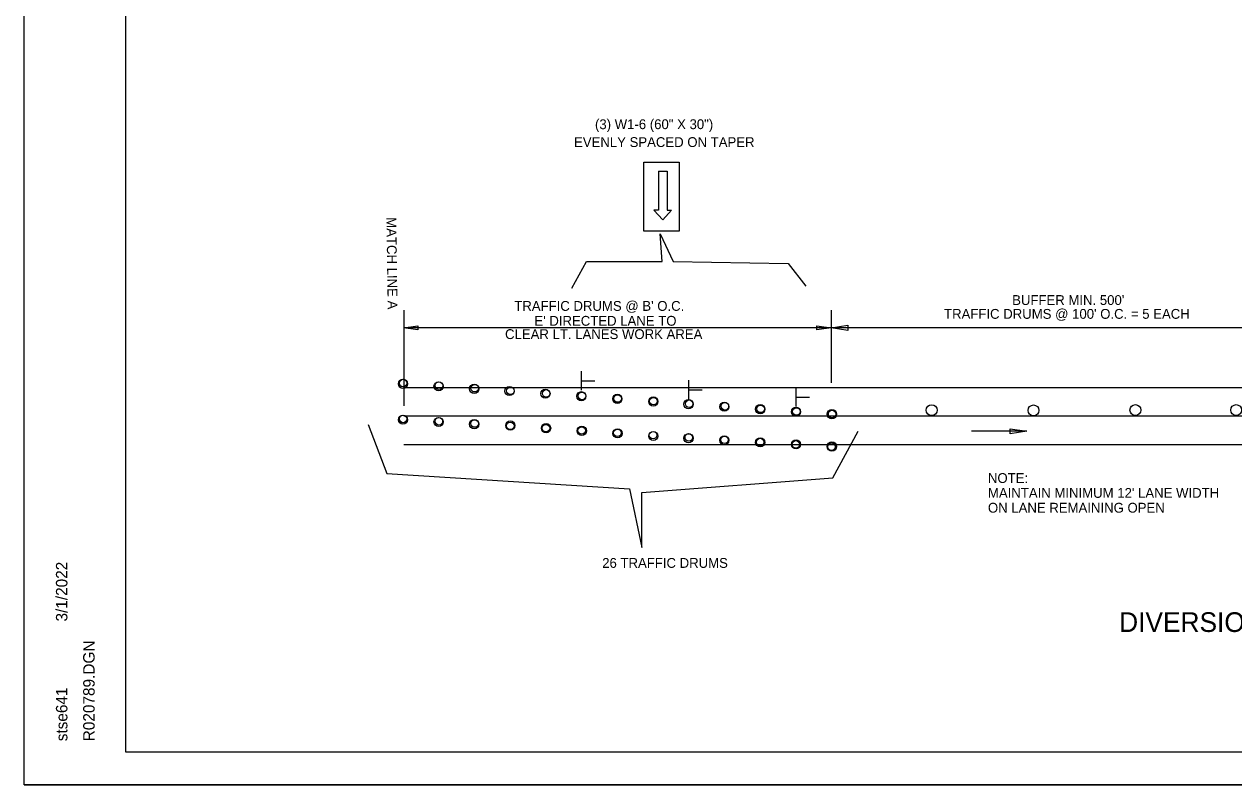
# Model space of a CAD drawing. Extents: x 1374897 to 1375063, y 381144 to 381251.
# Drawn here: x 1374896.6 to 1374970.4, y 381144.3 to 381190.7 of the extents above; entities that cross this region are included whole.
import ezdxf

# ---------------------------------------------------------------- set-up
doc = ezdxf.new("R2010")
doc.units = 0
for name, color, linetype in [('Default', 7, 'Continuous'), ('R_Border', 7, 'Continuous'), ('R_No Plot', 7, 'Continuous')]:
    doc.layers.add(name, color=color, linetype=linetype)

msp = doc.modelspace()

# ---------------------------------------------------------------- linework, layer by layer
at = {"layer": 'Default'}
for p, q in [((1374935.259, 381181.711), (1374935.259, 381179.321)), ((1374935.259, 381181.711), (1374935.791, 381181.711)), ((1374935.791, 381181.711), (1374935.791, 381179.321)), ((1374935.259, 381179.321), (1374934.993, 381179.321)), ((1374934.993, 381179.321), (1374935.525, 381178.737)), ((1374935.525, 381178.737), (1374936.058, 381179.321)), ((1374935.791, 381179.321), (1374936.058, 381179.321)), ((1374919.738, 381173.23), (1374919.738, 381167.401)), ((1374945.797, 381173.23), (1374945.797, 381168.801)), ((1374919.719, 381172.151), (1374920.588, 381172.282)), ((1374945.797, 381172.151), (1374919.719, 381172.151)), ((1374920.588, 381172.021), (1374919.719, 381172.151)), ((1374920.588, 381172.282), (1374920.588, 381172.021)), ((1374944.927, 381172.021), (1374944.927, 381172.282)), ((1374944.927, 381172.282), (1374945.797, 381172.151)), ((1374945.797, 381172.151), (1374944.927, 381172.021)), ((1374945.797, 381172.151), (1374946.827, 381172.306)), ((1374976.707, 381172.151), (1374945.797, 381172.151)), ((1374946.827, 381171.997), (1374945.797, 381172.151)), ((1374946.827, 381172.306), (1374946.827, 381171.997)), ((1374919.738, 381171.707), (1374919.738, 381167.401)), ((1374930.578, 381168.344), (1374930.578, 381169.505)), ((1374919.738, 381168.514), (1374946.643, 381168.514)), ((1374930.595, 381168.922), (1374931.388, 381168.922)), ((1374937.12, 381167.802), (1374937.12, 381168.963)), ((1374937.137, 381168.38), (1374937.929, 381168.38)), ((1374943.676, 381167.351), (1374943.676, 381168.512)), ((1374945.816, 381168.514), (1374972.709, 381168.514)), ((1374943.693, 381167.929), (1374944.486, 381167.929)), ((1374919.738, 381166.776), (1374947.02, 381166.776)), ((1374945.726, 381166.776), (1374972.927, 381166.776)), ((1374957.745, 381165.843), (1374954.366, 381165.843)), ((1374956.715, 381165.688), (1374956.715, 381165.997)), ((1374956.715, 381165.997), (1374957.745, 381165.843)), ((1374957.745, 381165.843), (1374956.715, 381165.688)), ((1374919.738, 381165.037), (1374947.362, 381165.037)), ((1374945.775, 381165.037), (1374973.281, 381165.037))]:
    msp.add_line(p, q, dxfattribs=at)
msp.add_lwpolyline([(1374934.383, 381178.054), (1374934.383, 381182.245), (1374936.527, 381182.245), (1374936.527, 381178.054)], close=True, dxfattribs=at)
for points in [[(1374929.974, 381174.568), (1374930.874, 381176.199), (1374935.498, 381176.199), (1374935.377, 381177.887), (1374936.158, 381176.199), (1374943.183, 381176.082), (1374944.263, 381174.685)], [(1374917.558, 381166.264), (1374918.686, 381163.273), (1374933.496, 381162.325), (1374934.247, 381158.75), (1374934.247, 381162.106), (1374945.896, 381163.009), (1374947.45, 381165.842)]]:
    msp.add_lwpolyline(points, dxfattribs=at)
for centre, radius in [((1374919.68, 381168.739), 0.281), ((1374919.68, 381168.785), 0.229), ((1374919.692, 381168.784), 0.229), ((1374921.853, 381168.587), 0.281), ((1374921.873, 381168.627), 0.229), ((1374924.026, 381168.435), 0.281), ((1374924.054, 381168.469), 0.229), ((1374926.174, 381168.298), 0.281), ((1374926.234, 381168.311), 0.229), ((1374928.368, 381168.139), 0.281), ((1374928.415, 381168.154), 0.229), ((1374930.562, 381167.979), 0.281), ((1374930.596, 381167.996), 0.229), ((1374932.756, 381167.82), 0.281), ((1374932.776, 381167.839), 0.229), ((1374934.95, 381167.661), 0.281), ((1374934.957, 381167.681), 0.229), ((1374937.099, 381167.496), 0.281), ((1374937.138, 381167.524), 0.229), ((1374939.286, 381167.343), 0.281), ((1374939.318, 381167.366), 0.229), ((1374941.473, 381167.191), 0.281), ((1374941.499, 381167.209), 0.229), ((1374943.66, 381167.039), 0.281), ((1374943.68, 381167.051), 0.229), ((1374945.847, 381166.886), 0.281), ((1374945.848, 381166.894), 0.229), ((1374945.86, 381166.893), 0.229), ((1374951.932, 381167.129), 0.333), ((1374958.146, 381167.114), 0.333), ((1374964.36, 381167.135), 0.333), ((1374970.508, 381167.136), 0.333), ((1374919.68, 381166.551), 0.281), ((1374919.68, 381166.596), 0.229), ((1374919.692, 381166.595), 0.229), ((1374921.853, 381166.412), 0.281), ((1374921.87, 381166.454), 0.229), ((1374924.026, 381166.274), 0.281), ((1374924.048, 381166.313), 0.229), ((1374926.23, 381166.192), 0.281), ((1374926.226, 381166.172), 0.229), ((1374928.41, 381166.033), 0.281), ((1374928.403, 381166.031), 0.229), ((1374930.59, 381165.874), 0.281), ((1374930.581, 381165.89), 0.229), ((1374932.77, 381165.715), 0.281), ((1374932.759, 381165.749), 0.229), ((1374934.95, 381165.555), 0.281), ((1374934.937, 381165.608), 0.229), ((1374937.099, 381165.418), 0.281), ((1374937.115, 381165.467), 0.229), ((1374939.286, 381165.293), 0.281), ((1374939.293, 381165.326), 0.229), ((1374941.473, 381165.168), 0.281), ((1374941.47, 381165.185), 0.229), ((1374943.66, 381165.044), 0.281), ((1374943.648, 381165.044), 0.229), ((1374945.847, 381164.919), 0.281), ((1374945.814, 381164.904), 0.229), ((1374945.826, 381164.903), 0.229)]:
    msp.add_circle(centre, radius, dxfattribs=at)
at = {"layer": 'R_Border'}
for p, q in [((1374902.775, 381146.28), (1374902.775, 381249.01)), ((1374902.775, 381146.28), (1374902.775, 381146.28)), ((1375060.865, 381146.28), (1374902.775, 381146.28))]:
    msp.add_line(p, q, dxfattribs=at)
at = {"layer": 'R_No Plot'}
msp.add_line((1374896.575, 381144.291), (1375063.241, 381144.291), dxfattribs=at)
for points in [[(1374896.571, 381250.958), (1375063.241, 381250.958), (1375063.241, 381144.289), (1374896.571, 381144.289)], [(1375019.735, 381249.01), (1375029.545, 381249.01), (1375029.545, 381244.07), (1375037.601, 381244.07), (1375049.201, 381244.07), (1375049.201, 381231.904), (1375060.865, 381231.904), (1375060.865, 381146.28), (1374902.775, 381146.28), (1374902.775, 381249.01)]]:
    msp.add_lwpolyline(points, close=True, dxfattribs=at)

# ---------------------------------------------------------------- texts
at = {"layer": 'Default'}
for s, rotation, p in [('(3) W1-6 (60" X 30")', 0.00754, (1374931.393, 381184.265)), ('EVENLY SPACED ON TAPER', 0.00754, (1374930.115, 381183.174)), ('MATCH LINE A', 270.80593, (1374918.669, 381178.891))]:
    msp.add_text(s, height=0.6, rotation=rotation, dxfattribs=at).set_placement(p)
for s, height, p in [("TRAFFIC DRUMS @ B' O.C.", 0.6, (1374926.47, 381173.186)), ("BUFFER MIN. 500'", 0.6, (1374956.844, 381173.545)), ("E' DIRECTED LANE TO", 0.6, (1374927.698, 381172.278)), ("TRAFFIC DRUMS @ 100' O.C. = 5 EACH", 0.6, (1374952.689, 381172.701)), ('CLEAR LT. LANES WORK AREA', 0.6, (1374925.907, 381171.466)), ('NOTE:', 0.6, (1374955.366, 381162.691)), ("MAINTAIN MINIMUM 12' LANE WIDTH", 0.6, (1374955.366, 381161.786)), ('ON LANE REMAINING OPEN', 0.6, (1374955.366, 381160.881)), ('26 TRAFFIC DRUMS', 0.6, (1374931.833, 381157.516)), ('DIVERSION FOR LT. LANE WORK ZONE', 1.2, (1374963.37, 381153.608))]:
    msp.add_text(s, height=height, dxfattribs=at).set_placement(p)
at = {"layer": 'R_Border'}
for s, p in [('3/1/2022', (1374899.208, 381154.244)), ('R020789.DGN', (1374900.87, 381146.943)), ('stse641', (1374899.208, 381146.943))]:
    msp.add_text(s, height=0.7, rotation=90, dxfattribs=at).set_placement(p)

doc.saveas('drawing.dxf')
